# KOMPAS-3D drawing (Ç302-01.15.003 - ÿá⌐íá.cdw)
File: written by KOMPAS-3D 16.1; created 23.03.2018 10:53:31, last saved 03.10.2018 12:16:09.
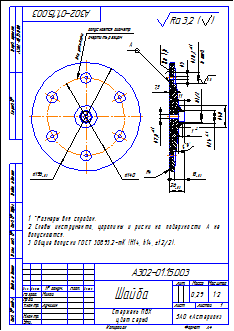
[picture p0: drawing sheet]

Sheet 1: A4, portrait

Title block, sheet 1: name: Шайба; designation: А302-01.15.003; mass: 0,29; scale: 1:2; sheets: 1; organisation: ЗАО «Астерион»; sheet format: A4; stored path: \\192.168.87.28\Konstructor_doc\Мембранные насосы\Мембранный электропривод\А302-00.00.000 - ASTRA-302 (МЭ200)\Чертежи\А302-00.15.003 - Шайба.cdw; drawn by: Милов; technical control: Лучихин

Views: Вид 1, Местный разрез 1, Спереди, Проекционный вид 2
Referenced files in Z:\Мембранные насосы\Мембранный электропривод\А302-00.00.000 - ASTRA-302 (МЭ200)\3Д ПВХ\: А302-01.15.003 - Шайба.m3d
Referenced files in Z:\Мембранные насосы\Мембранный электропривод\А302-00.00.000 - ASTRA-302 (МЭ200)\3Д\: А302-00.15.003 - Шайба.m3d
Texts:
  Стержень ПВХ
  цвет серый
  Ra 1,6
  допускается диаметр
  очертить резцом
  для разметки
  *Размеры для справок.
  Следы инструмента, царапины и риски на поверхности  А  не
  допускаются.
  Общие допуски ГОСТ 30893.2-mK (H14, h14,  t2/2).
  Ra 3,2
  Ra 3,2 ( )
Dimensions and other numbers on the sheet: 7,5; 7,8; 4; 5; 20,2; 6 отв.; 0,8; 24; 40; 26; 18; 11; 1; 140; 196; 1:2; 0,29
